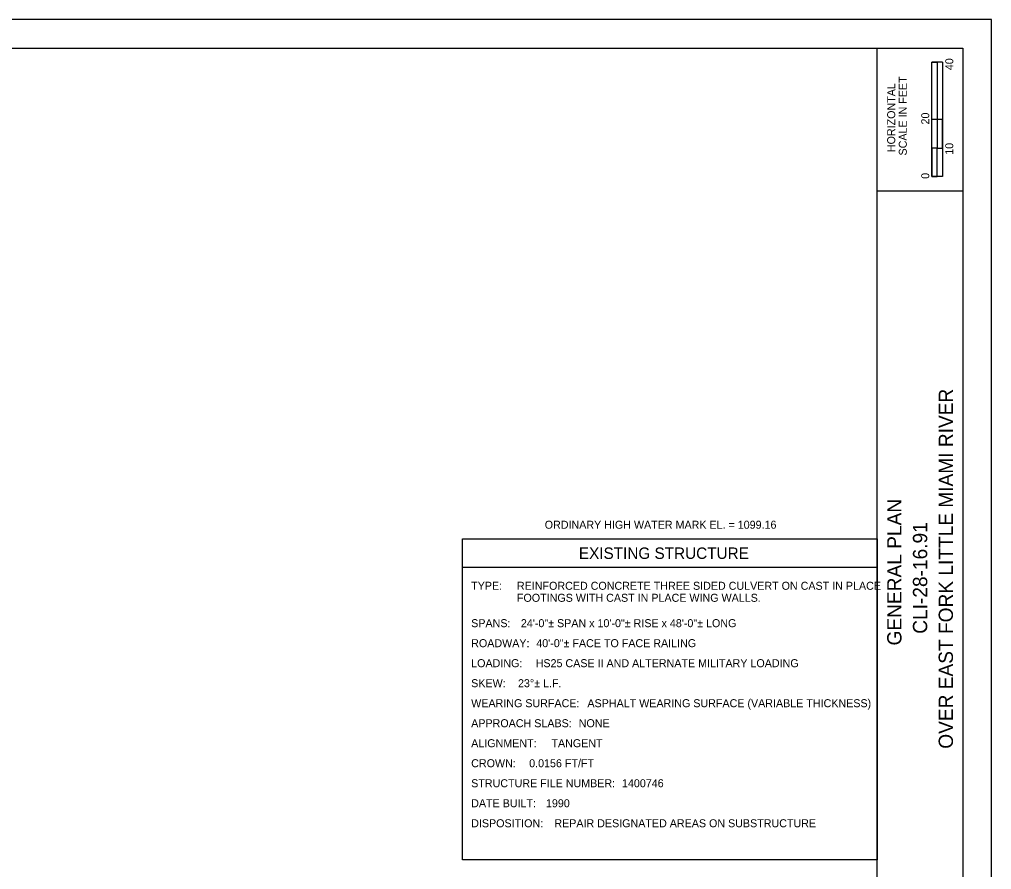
# Model space of a CAD drawing. Extents: x 0 to 680, y -49 to 440.
# Drawn here: x 340 to 680, y 142.6 to 440 of the extents above; entities that cross this region are included whole.
import ezdxf

# ---------------------------------------------------------------- set-up
doc = ezdxf.new("R2010")
doc.units = 0
for name, color, linetype in [('SN_X_Public', 7, 'Continuous'), ('SV_X_Shot_Marker', 7, 'Continuous'), ('UT_X_Misc_Cells', 7, 'Continuous'), ('VG_X_Cells', 7, 'Continuous')]:
    doc.layers.add(name, color=color, linetype=linetype)

msp = doc.modelspace()

# ---------------------------------------------------------------- linework, layer by layer
at = {"layer": 'SV_X_Shot_Marker'}
for p, q in [((640, 10), (640, 430)), ((640, 380), (670, 380))]:
    msp.add_line(p, q, dxfattribs=at)
msp.add_lwpolyline([(30, 430), (670, 430), (670, 10), (30, 10)], close=True, dxfattribs=at)
at = {"layer": 'UT_X_Misc_Cells'}
for p, q in [((659.13, 405), (659.13, 425)), ((659.13, 425), (661, 425)), ((659.13, 385), (659.13, 425)), ((662.88, 425), (659.13, 425)), ((661, 425), (661.02, 425)), ((661.02, 425), (661.02, 405)), ((662.88, 425), (662.88, 385)), ((661.02, 405), (659.13, 405)), ((662.87, 405), (661, 405)), ((661, 405), (661, 395)), ((662.87, 395), (662.87, 405)), ((661, 395), (659.13, 395)), ((659.13, 395), (659.13, 385)), ((661, 395), (662.87, 395)), ((661, 385), (661, 395)), ((662.88, 385), (659.13, 385)), ((659.13, 385), (661, 385)), ((640, 248.27), (495, 248.27))]:
    msp.add_line(p, q, dxfattribs=at)
msp.add_lwpolyline([(495, 258.27), (640, 258.27), (640, 145.98), (495, 145.98)], close=True, dxfattribs=at)
at = {"layer": 'VG_X_Cells'}
msp.add_lwpolyline([(0, 0), (680, 0), (680, 440), (0, 440)], close=True, dxfattribs=at)

# ---------------------------------------------------------------- texts
at = {"layer": 'SN_X_Public'}
for s, p in [('ORDINARY HIGH WATER MARK EL. = 1099.16', (523.72, 261.83)), ('REINFORCED CONCRETE THREE SIDED CULVERT ON CAST IN PLACE ', (514, 240.47)), ('FOOTINGS WITH CAST IN PLACE WING WALLS.', (514, 236.27)), ('24\'-0"± SPAN x 10\'-0"± RISE x 48\'-0"± LONG', (515.39, 227.39)), ('40\'-0"± FACE TO FACE RAILING', (520.77, 220.39)), ('HS25 CASE II AND ALTERNATE MILITARY LOADING', (520.56, 213.39)), ('23°± L.F.', (514.37, 206.39)), ('ASPHALT WEARING SURFACE (VARIABLE THICKNESS)', (538.65, 199.39)), ('NONE', (535.61, 192.39)), ('TANGENT', (526.07, 185.39)), ('0.0156 FT/FT', (518.28, 178.39)), ('1400746', (550.74, 171.39)), ('1990', (524.15, 164.39)), ('REPAIR DESIGNATED AREAS ON SUBSTRUCTURE', (527.09, 157.39))]:
    msp.add_text(s, height=2.8, dxfattribs=at).set_placement(p)
at = {"layer": 'UT_X_Misc_Cells'}
for s, height, p in [('40', 2.8, (666.61, 422.25)), ('SCALE IN FEET', 2.8, (650.35, 392.41)), ('HORIZONTAL', 2.8, (646.3, 393.58)), ('20', 2.8, (658.21, 403.25)), ('10', 2.8, (666.61, 392.65)), ('0', 2.8, (658.21, 384.23)), ('OVER EAST FORK LITTLE MIAMI RIVER', 5, (666.5, 184.86)), ('GENERAL PLAN', 5, (648.5, 220.98)), ('CLI-28-16.91', 5, (657.5, 225.08))]:
    msp.add_text(s, height=height, rotation=90, dxfattribs=at).set_placement(p)
for s, height, p in [('EXISTING STRUCTURE', 4, (535.67, 251.27)), ('TYPE:', 2.8, (498, 240.47)), ('SPANS:', 2.8, (498, 227.39)), ('ROADWAY:', 2.8, (498, 220.39)), ('LOADING:', 2.8, (498, 213.39)), ('SKEW:', 2.8, (498, 206.39)), ('WEARING SURFACE:', 2.8, (498, 199.39)), ('APPROACH SLABS:', 2.8, (498, 192.39)), ('ALIGNMENT:', 2.8, (498, 185.39)), ('CROWN:', 2.8, (498, 178.39)), ('STRUCTURE FILE NUMBER:', 2.8, (498, 171.39)), ('DATE BUILT:', 2.8, (498, 164.39)), ('DISPOSITION:', 2.8, (498, 157.39))]:
    msp.add_text(s, height=height, dxfattribs=at).set_placement(p)

doc.saveas('drawing.dxf')
